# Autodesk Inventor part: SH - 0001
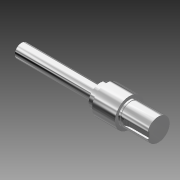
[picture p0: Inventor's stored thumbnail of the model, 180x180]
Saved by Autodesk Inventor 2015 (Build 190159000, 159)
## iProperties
Created: 2007-02
Part Number: SH - 0001
Material: Steel
Document SubType Name: Modeling
Designer: Autodesk, Inc.
Density: 7.85 g/cm^3
Mass: 3342.5 g
Surface Area: 452.362 cm^2
Volume: 425.796 cm^3
Description: Shaft - Fan 0062
Appearance: Chrome - Polished
CustomPartVersion: 1
Author: Autodesk, Inc.
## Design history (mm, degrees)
sketch "Main Sketch"
  geometry: L1 (0, 0)-(300.101, 0) reference; L2 (0, 0)-(0, 14.872); L3 (0, 14.872)-(172.339, 14.872); L4 (172.339, 14.872)-(172.339, 25.146); L5 (172.339, 25.146)-(186.309, 25.146); L6 (186.309, 25.146)-(186.309, 31.75); L7 (236.601, 31.75)-(236.601, 24.765); L8 (186.309, 31.75)-(236.601, 31.75); L9 (300.101, 24.765)-(300.101, 0); L10 (236.601, 24.765)-(300.101, 24.765)
  constraints: 20 end point, 6 horizontal, 5 vertical
  dimensions: "d3" = 29.7434 diameter of L3 L1 (derived); "d4" = 50.292 diameter of L5 L1 (derived); "d5" = 63.5 diameter of L8 L1 (derived); "d6" = 49.53 diameter of L10 L1 (derived)
revolve "Revolution1" sketch "Main Sketch" stored, may be unused: angle "d7" = 0 deg
feature "iFeature27:1"
feature "Shaft Keyway"
body "Solid1"
other parameters: "d0" = 0, "d1" = 0, "d2" = 0
